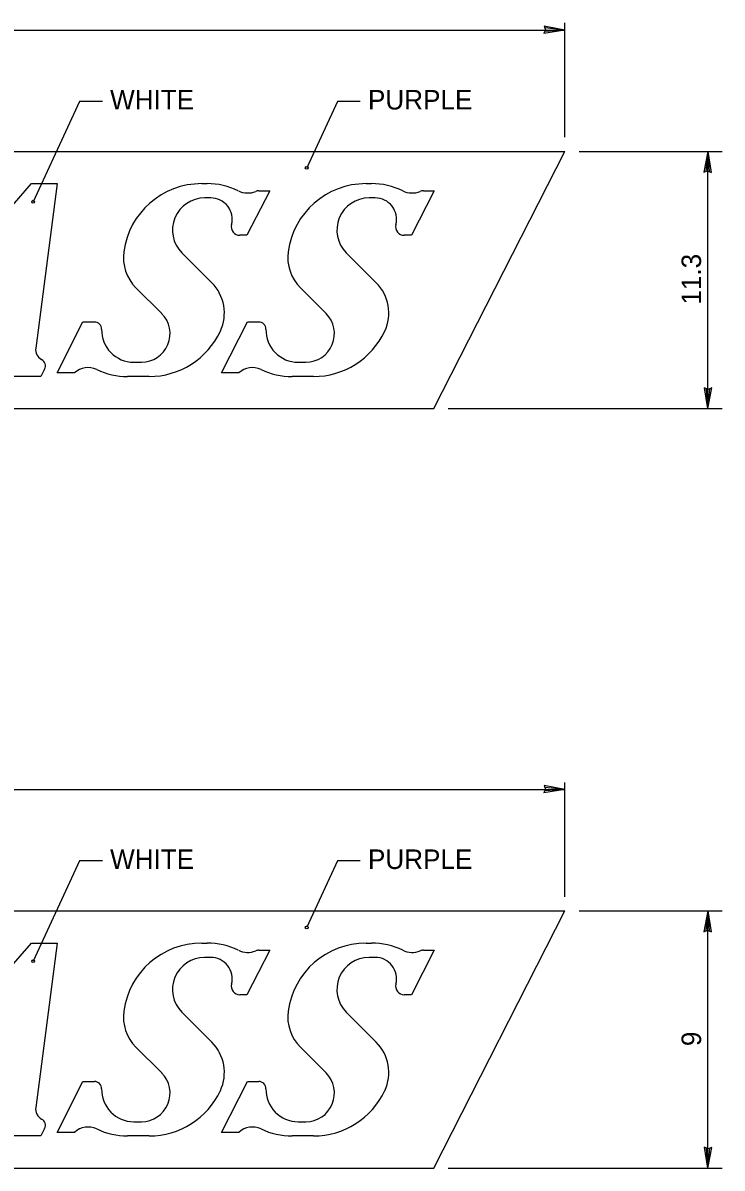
# Model space of a CAD drawing. Extents: x 10268197 to 10268826, y 2141503 to 2142677.
# Drawn here: x 10268525.45 to 10268547.09, y 2142369.86 to 2142405.33 of the extents above; entities that cross this region are included whole.
import ezdxf

# ---------------------------------------------------------------- set-up
doc = ezdxf.new("R2010")
doc.units = 0
for name, color, linetype in [('1', 7, 'Continuous'), ('Default', 7, 'Continuous'), ('GSBWFill', 7, 'Continuous')]:
    doc.layers.add(name, color=color, linetype=linetype)

msp = doc.modelspace()

# ---------------------------------------------------------------- linework, layer by layer
at = {"layer": '1'}
for p, q in [((10268542.219, 2142401.788), (10268542.219, 2142405.328)), ((10268523.019, 2142405.107), (10268542.219, 2142405.107)), ((10268527.203, 2142402.897), (10268525.764, 2142399.79)), ((10268527.906, 2142402.897), (10268527.203, 2142402.897)), ((10268535.184, 2142402.897), (10268534.23, 2142400.839)), ((10268535.886, 2142402.897), (10268535.184, 2142402.897)), ((10268542.661, 2142401.346), (10268547.085, 2142401.346)), ((10268546.643, 2142393.382), (10268546.643, 2142401.346)), ((10268538.603, 2142393.382), (10268547.085, 2142393.382)), ((10268542.219, 2142378.267), (10268542.219, 2142381.807)), ((10268523.019, 2142381.586), (10268542.219, 2142381.586)), ((10268527.203, 2142379.376), (10268525.764, 2142376.269)), ((10268527.906, 2142379.376), (10268527.203, 2142379.376)), ((10268535.184, 2142379.376), (10268534.23, 2142377.318)), ((10268535.886, 2142379.376), (10268535.184, 2142379.376)), ((10268542.661, 2142377.825), (10268547.085, 2142377.825)), ((10268546.643, 2142369.861), (10268546.643, 2142377.825)), ((10268538.603, 2142369.861), (10268547.085, 2142369.861))]:
    msp.add_line(p, q, dxfattribs=at)
for centre in [(10268534.23, 2142400.838), (10268525.764, 2142399.789), (10268534.23, 2142377.317), (10268525.764, 2142376.269)]:
    msp.add_circle(centre, 0.0442, dxfattribs=at)
at = {"layer": 'Default'}
for p, q in [((10268542.219, 2142405.107), (10268541.576, 2142405.231)), ((10268541.576, 2142405.231), (10268541.623, 2142405.117)), ((10268541.623, 2142405.117), (10268541.572, 2142405.004)), ((10268542.219, 2142405.107), (10268541.572, 2142405.004)), ((10268542.219, 2142405.107), (10268541.599, 2142405.063)), ((10268542.219, 2142405.107), (10268541.6, 2142405.171)), ((10268516.98, 2142401.346), (10268542.219, 2142401.346)), ((10268538.161, 2142393.382), (10268542.219, 2142401.346)), ((10268546.643, 2142401.346), (10268546.518, 2142400.703)), ((10268546.643, 2142401.346), (10268546.578, 2142400.728)), ((10268546.643, 2142401.346), (10268546.745, 2142400.699)), ((10268546.643, 2142401.346), (10268546.686, 2142400.726)), ((10268546.518, 2142400.703), (10268546.633, 2142400.75)), ((10268546.633, 2142400.75), (10268546.745, 2142400.699)), ((10268521.19, 2142395.154), (10268525.708, 2142400.35)), ((10268525.708, 2142400.35), (10268526.505, 2142400.35)), ((10268526.505, 2142400.35), (10268525.842, 2142395.259)), ((10268530.98, 2142400.35), (10268531.147, 2142400.35)), ((10268536.068, 2142400.35), (10268536.235, 2142400.35)), ((10268531.26, 2142399.908), (10268531.07, 2142399.908)), ((10268533.084, 2142400.129), (10268532.381, 2142398.749)), ((10268532.752, 2142400.129), (10268533.084, 2142400.129)), ((10268536.348, 2142399.908), (10268536.158, 2142399.908)), ((10268538.172, 2142400.129), (10268537.469, 2142398.749)), ((10268537.84, 2142400.129), (10268538.172, 2142400.129)), ((10268532.381, 2142398.749), (10268532.16, 2142398.749)), ((10268537.469, 2142398.749), (10268537.248, 2142398.749)), ((10268530.366, 2142398.209), (10268531.293, 2142397.281)), ((10268535.454, 2142398.209), (10268536.381, 2142397.281)), ((10268529.741, 2142396.331), (10268528.945, 2142397.127)), ((10268534.829, 2142396.331), (10268534.033, 2142397.127)), ((10268526.502, 2142394.489), (10268527.305, 2142396.065)), ((10268527.305, 2142396.065), (10268527.66, 2142396.065)), ((10268531.589, 2142394.489), (10268532.393, 2142396.065)), ((10268532.393, 2142396.065), (10268532.748, 2142396.065)), ((10268526.119, 2142394.605), (10268526.003, 2142394.377)), ((10268528.876, 2142394.82), (10268529.115, 2142394.82)), ((10268533.964, 2142394.82), (10268534.203, 2142394.82)), ((10268526.003, 2142394.377), (10268523.791, 2142394.377)), ((10268527.039, 2142394.489), (10268526.502, 2142394.489)), ((10268529.353, 2142394.377), (10268528.688, 2142394.377)), ((10268532.127, 2142394.489), (10268531.589, 2142394.489)), ((10268534.441, 2142394.377), (10268533.775, 2142394.377)), ((10268546.643, 2142393.382), (10268546.54, 2142394.029)), ((10268546.653, 2142393.978), (10268546.54, 2142394.029)), ((10268546.643, 2142393.382), (10268546.6, 2142394.002)), ((10268546.643, 2142393.382), (10268546.768, 2142394.025)), ((10268546.643, 2142393.382), (10268546.707, 2142394)), ((10268546.768, 2142394.025), (10268546.653, 2142393.978)), ((10268516.394, 2142393.382), (10268538.161, 2142393.382)), ((10268541.623, 2142381.596), (10268541.572, 2142381.483)), ((10268542.219, 2142381.586), (10268541.572, 2142381.483)), ((10268542.219, 2142381.586), (10268541.576, 2142381.711)), ((10268541.576, 2142381.711), (10268541.623, 2142381.596)), ((10268542.219, 2142381.586), (10268541.599, 2142381.542)), ((10268542.219, 2142381.586), (10268541.6, 2142381.651)), ((10268516.98, 2142377.825), (10268542.219, 2142377.825)), ((10268538.161, 2142369.861), (10268542.219, 2142377.825)), ((10268546.643, 2142377.825), (10268546.518, 2142377.182)), ((10268546.643, 2142377.825), (10268546.578, 2142377.207)), ((10268546.643, 2142377.825), (10268546.745, 2142377.178)), ((10268546.643, 2142377.825), (10268546.686, 2142377.206)), ((10268546.518, 2142377.182), (10268546.633, 2142377.229)), ((10268546.633, 2142377.229), (10268546.745, 2142377.178)), ((10268521.19, 2142371.634), (10268525.708, 2142376.829)), ((10268525.708, 2142376.829), (10268526.505, 2142376.829)), ((10268526.505, 2142376.829), (10268525.842, 2142371.738)), ((10268530.98, 2142376.829), (10268531.147, 2142376.829)), ((10268536.068, 2142376.829), (10268536.235, 2142376.829)), ((10268533.084, 2142376.608), (10268532.381, 2142375.228)), ((10268532.752, 2142376.608), (10268533.084, 2142376.608)), ((10268538.172, 2142376.608), (10268537.469, 2142375.228)), ((10268537.84, 2142376.608), (10268538.172, 2142376.608)), ((10268531.26, 2142376.387), (10268531.07, 2142376.387)), ((10268536.348, 2142376.387), (10268536.158, 2142376.387)), ((10268532.381, 2142375.228), (10268532.16, 2142375.228)), ((10268537.469, 2142375.228), (10268537.248, 2142375.228)), ((10268530.366, 2142374.688), (10268531.293, 2142373.76)), ((10268535.454, 2142374.688), (10268536.381, 2142373.76)), ((10268529.741, 2142372.81), (10268528.945, 2142373.606)), ((10268534.829, 2142372.81), (10268534.033, 2142373.606)), ((10268526.502, 2142370.968), (10268527.305, 2142372.544)), ((10268527.305, 2142372.544), (10268527.66, 2142372.544)), ((10268531.589, 2142370.968), (10268532.393, 2142372.544)), ((10268532.393, 2142372.544), (10268532.748, 2142372.544)), ((10268528.876, 2142371.299), (10268529.115, 2142371.299)), ((10268533.964, 2142371.299), (10268534.203, 2142371.299)), ((10268526.003, 2142370.856), (10268523.791, 2142370.856)), ((10268526.119, 2142371.085), (10268526.003, 2142370.856)), ((10268527.039, 2142370.968), (10268526.502, 2142370.968)), ((10268529.353, 2142370.856), (10268528.688, 2142370.856)), ((10268532.127, 2142370.968), (10268531.589, 2142370.968)), ((10268534.441, 2142370.856), (10268533.775, 2142370.856)), ((10268546.643, 2142369.861), (10268546.54, 2142370.508)), ((10268546.653, 2142370.457), (10268546.54, 2142370.508)), ((10268546.643, 2142369.861), (10268546.6, 2142370.481)), ((10268546.643, 2142369.861), (10268546.768, 2142370.504)), ((10268546.643, 2142369.861), (10268546.707, 2142370.479)), ((10268546.768, 2142370.504), (10268546.653, 2142370.457)), ((10268516.394, 2142369.861), (10268538.161, 2142369.861))]:
    msp.add_line(p, q, dxfattribs=at)
for centre, radius, start, end in [((10268530.979, 2142397.916), 2.433, 90, 172.3089), ((10268531.147, 2142398.138), 2.212, 64.0896, 90), ((10268536.067, 2142397.916), 2.433, 90, 172.3089), ((10268536.235, 2142398.138), 2.212, 64.0896, 90), ((10268531.07, 2142398.912), 0.995, 90, 225), ((10268531.26, 2142399.244), 0.664, 345.6915, 90), ((10268532.404, 2142400.724), 0.664, 244.0896, 292.0347), ((10268532.752, 2142399.863), 0.265, 90, 112.0347), ((10268536.158, 2142398.912), 0.995, 90, 225), ((10268536.348, 2142399.244), 0.664, 345.6915, 90), ((10268537.492, 2142400.724), 0.664, 244.0896, 292.0347), ((10268537.84, 2142399.863), 0.265, 90, 112.0347), ((10268532.16, 2142399.014), 0.265, 165.6915, 270), ((10268537.248, 2142399.014), 0.265, 165.6915, 270), ((10268529.883, 2142398.064), 1.327, 172.3089, 225), ((10268534.971, 2142398.064), 1.327, 172.3089, 225), ((10268530.355, 2142396.342), 1.327, 334.95, 45), ((10268535.443, 2142396.342), 1.327, 334.95, 45), ((10268529.115, 2142395.704), 0.885, 270, 45), ((10268534.203, 2142395.704), 0.885, 270, 45), ((10268527.66, 2142395.843), 0.221, 358.6664, 90), ((10268532.748, 2142395.843), 0.221, 358.6664, 90), ((10268528.876, 2142395.815), 0.995, 178.6665, 270), ((10268529.353, 2142396.81), 2.433, 270, 334.95), ((10268533.964, 2142395.815), 0.995, 178.6665, 270), ((10268534.441, 2142396.81), 2.433, 270, 334.95), ((10268526.193, 2142395.213), 0.354, 172.5884, 241.8673), ((10268525.922, 2142394.705), 0.221, 332.9784, 61.8673), ((10268527.463, 2142394.036), 0.619, 64.3795, 133.1892), ((10268528.687, 2142396.589), 2.212, 244.3795, 270), ((10268532.551, 2142394.036), 0.619, 64.3795, 133.1892), ((10268533.775, 2142396.589), 2.212, 244.3795, 270), ((10268530.979, 2142374.396), 2.433, 90, 172.3089), ((10268531.147, 2142374.617), 2.212, 64.0896, 90), ((10268536.067, 2142374.396), 2.433, 90, 172.3089), ((10268536.235, 2142374.617), 2.212, 64.0896, 90), ((10268532.404, 2142377.204), 0.664, 244.0896, 292.0347), ((10268532.752, 2142376.342), 0.265, 90, 112.0347), ((10268537.492, 2142377.204), 0.664, 244.0896, 292.0347), ((10268537.84, 2142376.342), 0.265, 90, 112.0347), ((10268531.07, 2142375.391), 0.995, 90, 225), ((10268531.26, 2142375.723), 0.664, 345.6915, 90), ((10268536.158, 2142375.391), 0.995, 90, 225), ((10268536.348, 2142375.723), 0.664, 345.6915, 90), ((10268532.16, 2142375.493), 0.265, 165.6915, 270), ((10268537.248, 2142375.493), 0.265, 165.6915, 270), ((10268529.883, 2142374.544), 1.327, 172.3089, 225), ((10268534.971, 2142374.544), 1.327, 172.3089, 225), ((10268530.355, 2142372.821), 1.327, 334.95, 45), ((10268535.443, 2142372.821), 1.327, 334.95, 45), ((10268529.115, 2142372.183), 0.885, 270, 45), ((10268534.203, 2142372.183), 0.885, 270, 45), ((10268527.66, 2142372.322), 0.221, 358.6664, 90), ((10268528.876, 2142372.294), 0.995, 178.6665, 270), ((10268529.353, 2142373.29), 2.433, 270, 334.95), ((10268532.748, 2142372.322), 0.221, 358.6664, 90), ((10268533.964, 2142372.294), 0.995, 178.6665, 270), ((10268534.441, 2142373.29), 2.433, 270, 334.95), ((10268526.193, 2142371.692), 0.354, 172.5884, 241.8673), ((10268525.922, 2142371.185), 0.221, 332.9784, 61.8673), ((10268527.463, 2142370.515), 0.619, 64.3795, 133.1892), ((10268532.551, 2142370.515), 0.619, 64.3795, 133.1892), ((10268528.687, 2142373.068), 2.212, 244.3795, 270), ((10268533.775, 2142373.068), 2.212, 244.3795, 270)]:
    msp.add_arc(centre, radius, start, end, dxfattribs=at)

# ---------------------------------------------------------------- texts
at = {"layer": '1'}
for s, p in [('WHITE', (10268528.145, 2142402.646)), ('PURPLE', (10268536.126, 2142402.646)), ('WHITE', (10268528.145, 2142379.125)), ('PURPLE', (10268536.126, 2142379.125))]:
    msp.add_text(s, height=0.6037, dxfattribs=at).set_placement(p)
for s, height, p in [('11.3', 0.6037, (10268546.435, 2142396.604)), ('9', 0.604, (10268546.435, 2142373.639))]:
    msp.add_text(s, height=height, rotation=90, dxfattribs=at).set_placement(p)
at = {"layer": 'GSBWFill'}
for s, p in [('reportName:OOCEA10', (10268534.381, 2142401.134)), ('tableTextHeight:0.0500', (10268534.381, 2142401.134)), ('letterPositions:2', (10268534.381, 2142401.134)), ('inchesDisplay:0', (10268534.381, 2142401.134)), ('plotScale:50', (10268534.382, 2142401.134))]:
    msp.add_text(s, height=0.000333, dxfattribs=at).set_placement(p)

doc.saveas('drawing.dxf')
